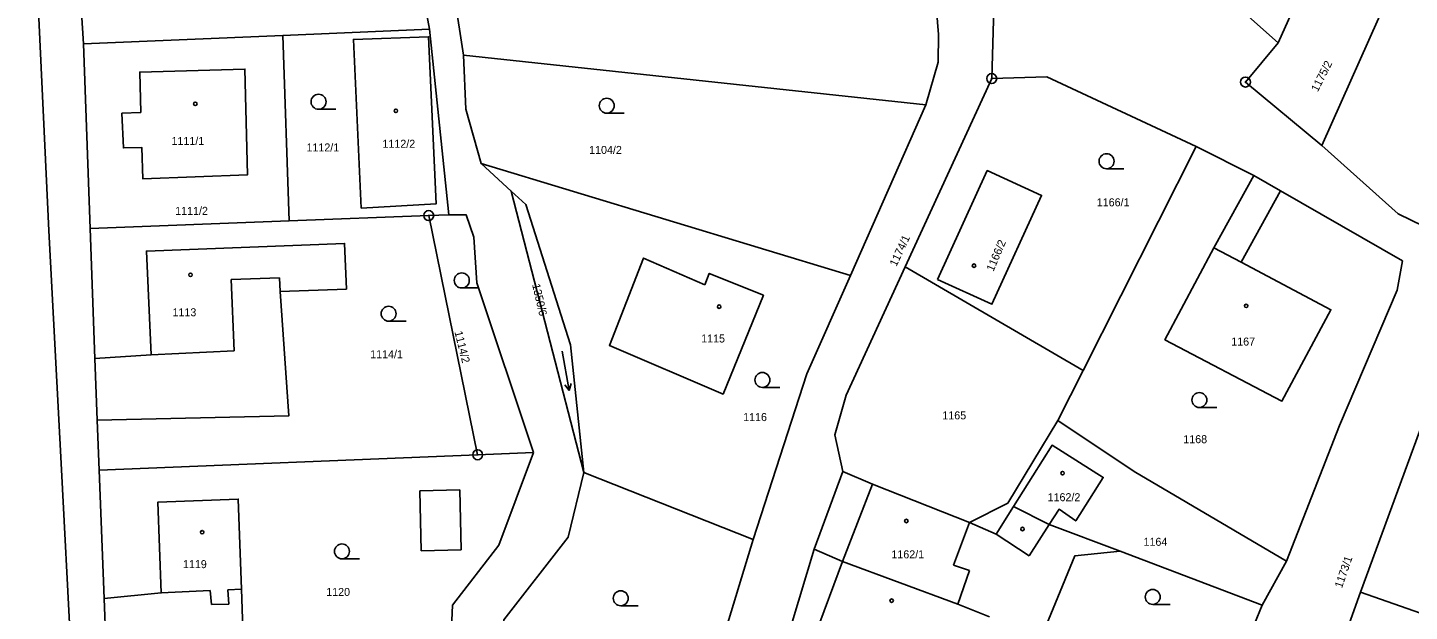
# Model space of a CAD drawing. Extents: x -587171 to -555306, y -1167727 to -1074732.
# Drawn here: x -560066 to -559927.4, y -1077139.7 to -1077081.2 of the extents above; entities that cross this region are included whole.
import ezdxf

# ---------------------------------------------------------------- set-up
doc = ezdxf.new("R2010")
doc.units = 0
for name, color, linetype in [('Hranice parcel', 7, 'Continuous'), ('Parcelní čísla', 7, 'Continuous'), ('Vnitřní kresba', 7, 'Continuous'), ('Značky bodu BP', 7, 'Continuous'), ('Značky budov', 7, 'Continuous'), ('Značky kultur', 7, 'Continuous')]:
    doc.layers.add(name, color=color, linetype=linetype)

msp = doc.modelspace()

# ---------------------------------------------------------------- linework, layer by layer
at = {"layer": 'Hranice parcel'}
for p, q in [((-560025.65, -1077081.36), (-560029.13, -1077063.25)), ((-560025.58, -1077062.46), (-560022.24, -1077083.94)), ((-560061.59, -1077064.02), (-560060.37, -1077082.81)), ((-559968.75, -1077069), (-559969.27, -1077086.3)), ((-559940.53, -1077082.73), (-559936, -1077072.54)), ((-559928.12, -1077074.97), (-559936.14, -1077093.02)), ((-560060.37, -1077082.81), (-560040.38, -1077081.98)), ((-560040.38, -1077081.98), (-560025.65, -1077081.36)), ((-560039.73, -1077100.58), (-560040.38, -1077081.98)), ((-560023.73, -1077099.96), (-560025.65, -1077081.36)), ((-560060.37, -1077082.81), (-560059.71, -1077101.35)), ((-560022.24, -1077083.94), (-559975.87, -1077088.92)), ((-559977.95, -1077105.17), (-559969.27, -1077086.3)), ((-559983.42, -1077106.05), (-559975.87, -1077088.92)), ((-559948.77, -1077093.13), (-559960.11, -1077115.58)), ((-559942.99, -1077096.02), (-559948.77, -1077093.13)), ((-560020.47, -1077094.81), (-559983.42, -1077106.05)), ((-560020.47, -1077094.81), (-560017.46, -1077097.59)), ((-559942.99, -1077096.02), (-559946.99, -1077103.27)), ((-559940.3, -1077097.56), (-559942.99, -1077096.02)), ((-560010.17, -1077125.81), (-560017.46, -1077097.59)), ((-559944.25, -1077104.72), (-559940.3, -1077097.56)), ((-559928.05, -1077104.59), (-559940.3, -1077097.56)), ((-560059.71, -1077101.35), (-560039.73, -1077100.58)), ((-560025.74, -1077100.04), (-560039.73, -1077100.58)), ((-560023.73, -1077099.96), (-560025.74, -1077100.04)), ((-560020.83, -1077124.03), (-560025.74, -1077100.04)), ((-560059.71, -1077101.35), (-560059.22, -1077114.39)), ((-559960.11, -1077115.58), (-559977.95, -1077105.17)), ((-560059.22, -1077114.39), (-560058.99, -1077120.55)), ((-559962.65, -1077120.6), (-559960.11, -1077115.58)), ((-560058.99, -1077120.55), (-560058.8, -1077125.56)), ((-560058.8, -1077125.56), (-560020.83, -1077124.03)), ((-560020.83, -1077124.03), (-560015.23, -1077123.81)), ((-560058.8, -1077125.56), (-560058.29, -1077138.46)), ((-560010.17, -1077125.81), (-559993.18, -1077132.53)), ((-559987.08, -1077133.51), (-559984.2, -1077125.72)), ((-559963.5, -1077131.03), (-559967.08, -1077129.22)), ((-559963.5, -1077131.03), (-559956.37, -1077133.7)), ((-560001.14, -1077158.62), (-559993.18, -1077132.53)), ((-559987.08, -1077133.51), (-559989.4, -1077141.14)), ((-559942.15, -1077139.11), (-559956.37, -1077133.7)), ((-559942.15, -1077139.11), (-559939.69, -1077134.69)), ((-559932.27, -1077137.8), (-559943.92, -1077169.97)), ((-559932.27, -1077137.8), (-559867.06, -1077160.72)), ((-560058.29, -1077138.46), (-560057.93, -1077147.65)), ((-559946.53, -1077149.71), (-559942.15, -1077139.11))]:
    msp.add_line(p, q, dxfattribs=at)
for points in [[(-559975.87, -1077088.92), (-559974.63, -1077084.66), (-559974.61, -1077081.87), (-559975.45, -1077071.52), (-559979.26, -1077056.83)], [(-559940.53, -1077082.73), (-559943.5, -1077080.07), (-559946.57, -1077077.52), (-559949.8, -1077075.14), (-559953.72, -1077072.62), (-559953.01, -1077070.87)], [(-560032.51, -1077099.3), (-560033.3, -1077082.38), (-560025.75, -1077082.11), (-560025, -1077098.87), (-560032.51, -1077099.3)], [(-560022.24, -1077083.94), (-560022, -1077089.38), (-560020.47, -1077094.81)], [(-559936.14, -1077093.02), (-559943.82, -1077086.65), (-559940.53, -1077082.73)], [(-560054.62, -1077089.69), (-560056.52, -1077089.78), (-560056.37, -1077093.26), (-560054.52, -1077093.2), (-560054.43, -1077096.35), (-560043.92, -1077095.97), (-560044.18, -1077085.35), (-560054.73, -1077085.65), (-560054.62, -1077089.69)], [(-559969.27, -1077086.3), (-559963.73, -1077086.13), (-559948.77, -1077093.13)], [(-559919.63, -1077104.19), (-559928.5, -1077099.87), (-559936.14, -1077093.02)], [(-559974.7, -1077106.44), (-559969.72, -1077095.53), (-559964.26, -1077098.02), (-559969.24, -1077108.93), (-559974.7, -1077106.44)], [(-560017.46, -1077097.59), (-560016, -1077098.93), (-560011.53, -1077113), (-560010.17, -1077125.81)], [(-560015.23, -1077123.81), (-560020.9, -1077106.78), (-560021.22, -1077102.2), (-560021.99, -1077099.95), (-560023.73, -1077099.96)], [(-560058.99, -1077120.55), (-560039.78, -1077120.14), (-560040.64, -1077107.67), (-560034, -1077107.41), (-560034.17, -1077102.83), (-560054.05, -1077103.61), (-560053.58, -1077114.01), (-560059.22, -1077114.39)], [(-559946.99, -1077103.27), (-559951.89, -1077112.49), (-559940.16, -1077118.64), (-559935.25, -1077109.48), (-559944.25, -1077104.72)], [(-559998.06, -1077106.98), (-560004.18, -1077104.31), (-560007.61, -1077113.07), (-559996.21, -1077117.95), (-559992.16, -1077108.04), (-559997.6, -1077105.85), (-559998.06, -1077106.98)], [(-559939.69, -1077134.69), (-559934.37, -1077121.11), (-559928.59, -1077107.52), (-559928.05, -1077104.59)], [(-559993.18, -1077132.53), (-559987.82, -1077115.9), (-559983.42, -1077106.05)], [(-559977.95, -1077105.17), (-559983.87, -1077118.06), (-559985, -1077122.04), (-559984.2, -1077125.72)], [(-559858.06, -1077126.03), (-559921.63, -1077108.87), (-559932.27, -1077137.8)], [(-559962.65, -1077120.6), (-559967.64, -1077128.87), (-559971.5, -1077130.82)], [(-559939.69, -1077134.69), (-559954.98, -1077125.71), (-559962.65, -1077120.6)], [(-560023.74, -1077148.28), (-560023.37, -1077139.12), (-560018.7, -1077133.08), (-560015.23, -1077123.81)], [(-559967.08, -1077129.22), (-559963.21, -1077123.07), (-559958.08, -1077126.3), (-559960.84, -1077130.66), (-559962.51, -1077129.49), (-559963.5, -1077131.03)], [(-560010.17, -1077125.81), (-560011.75, -1077132.31), (-560018.2, -1077140.57), (-560017.83, -1077148.74)], [(-559984.2, -1077125.72), (-559981.21, -1077126.99), (-559971.5, -1077130.82)], [(-560057.93, -1077147.65), (-560044.25, -1077145.49), (-560044.53, -1077137.5), (-560044.84, -1077128.48), (-560052.9, -1077128.77), (-560052.57, -1077137.88), (-560058.29, -1077138.46)], [(-559971.5, -1077130.82), (-559968.81, -1077131.98), (-559967.08, -1077129.22)], [(-559969.49, -1077140.3), (-559972.67, -1077139), (-559984.22, -1077134.73), (-559987.08, -1077133.51)], [(-559956.37, -1077133.7), (-559960.94, -1077134.18), (-559964.56, -1077143.04)]]:
    msp.add_lwpolyline(points, dxfattribs=at)
at = {"layer": 'Vnitřní kresba'}
for p, q in [((-560065.97, -1077055.87), (-560063.86, -1077101.54)), ((-560063.86, -1077101.54), (-560062.58, -1077125.54)), ((-559946.99, -1077103.27), (-559944.25, -1077104.72)), ((-560040.7, -1077106.27), (-560045.55, -1077106.45)), ((-560040.64, -1077107.67), (-560040.7, -1077106.27)), ((-560045.55, -1077106.45), (-560045.24, -1077113.61)), ((-560045.24, -1077113.61), (-560053.58, -1077114.01)), ((-560062.58, -1077125.54), (-560061.31, -1077149.62)), ((-559981.21, -1077126.99), (-559984.22, -1077134.73)), ((-560026.63, -1077127.64), (-560022.62, -1077127.56)), ((-560026.5, -1077133.65), (-560026.63, -1077127.64)), ((-560022.62, -1077127.56), (-560022.5, -1077133.58)), ((-559971.5, -1077130.82), (-559973.1, -1077135.1)), ((-559963.5, -1077131.03), (-559965.51, -1077134.17)), ((-559965.51, -1077134.17), (-559968.81, -1077131.98)), ((-560022.5, -1077133.58), (-560026.5, -1077133.65)), ((-559984.22, -1077134.73), (-559986.95, -1077142.03)), ((-559973.1, -1077135.1), (-559971.51, -1077135.65)), ((-559971.51, -1077135.65), (-559972.67, -1077139)), ((-560047.65, -1077137.65), (-560052.57, -1077137.88)), ((-560047.54, -1077139.05), (-560047.65, -1077137.65)), ((-560044.53, -1077137.5), (-560045.9, -1077137.56)), ((-560045.9, -1077137.56), (-560045.8, -1077139)), ((-560045.8, -1077139), (-560047.54, -1077139.05))]:
    msp.add_line(p, q, dxfattribs=at)
at = {"layer": 'Značky bodu BP'}
for centre, radius in [((-559969.27, -1077086.3), 0.5), ((-559969.27, -1077086.3), 0.0303), ((-559943.82, -1077086.65), 0.5), ((-559943.82, -1077086.65), 0.0303), ((-560025.74, -1077100.04), 0.5), ((-560025.74, -1077100.04), 0.0303), ((-560020.83, -1077124.03), 0.5), ((-560020.83, -1077124.03), 0.0303)]:
    msp.add_circle(centre, radius, dxfattribs=at)
at = {"layer": 'Značky budov'}
for centre in [(-560049.15, -1077088.84), (-560029.03, -1077089.53), (-559971.04, -1077105.07), (-560049.64, -1077105.99), (-559996.6, -1077109.18), (-559943.74, -1077109.1), (-559962.16, -1077125.87), (-559977.83, -1077130.67), (-560048.47, -1077131.8), (-559966.18, -1077131.48), (-559979.31, -1077138.66)]:
    msp.add_circle(centre, 0.175, dxfattribs=at)
at = {"layer": 'Značky kultur'}
for p, q in [((-560036.79, -1077089.38), (-560035.04, -1077089.38)), ((-560007.88, -1077089.77), (-560006.13, -1077089.77)), ((-559957.75, -1077095.34), (-559956, -1077095.34)), ((-560022.42, -1077107.3), (-560020.67, -1077107.3)), ((-560029.76, -1077110.63), (-560028.01, -1077110.63)), ((-560012.35, -1077113.63), (-560011.66, -1077117.59)), ((-560011.66, -1077117.59), (-560012.1, -1077117.01)), ((-560011.66, -1077117.59), (-560011.44, -1077116.89)), ((-559992.27, -1077117.28), (-559990.52, -1077117.28)), ((-559948.44, -1077119.29), (-559946.69, -1077119.29)), ((-560034.44, -1077134.47), (-560032.69, -1077134.47)), ((-560006.48, -1077139.17), (-560004.73, -1077139.17)), ((-559953.12, -1077139.04), (-559951.37, -1077139.04))]:
    msp.add_line(p, q, dxfattribs=at)
for centre in [(-560036.79, -1077088.63), (-560007.88, -1077089.02), (-559957.75, -1077094.59), (-560022.42, -1077106.55), (-560029.76, -1077109.88), (-559992.27, -1077116.53), (-559948.44, -1077118.54), (-560034.44, -1077133.72), (-560006.48, -1077138.42), (-559953.12, -1077138.29)]:
    msp.add_circle(centre, 0.75, dxfattribs=at)

# ---------------------------------------------------------------- texts
at = {"layer": 'Parcelní čísla'}
for s, rotation, p in [('1175/2', 63, (-559936.57, -1077087.69)), ('1174/1', 65, (-559978.83, -1077105.21)), ('1166/2', 67, (-559969.1, -1077105.71)), ('1350/6', 283, (-560015.37, -1077106.97)), ('1114/2', 284, (-560023.16, -1077111.72)), ('1173/1', 71, (-559934.14, -1077137.46))]:
    msp.add_text(s, height=0.803, rotation=rotation, dxfattribs=at).set_placement(p)
for s, p in [('1111/1', (-560051.54, -1077092.96)), ('1112/2', (-560030.38, -1077093.24)), ('1112/1', (-560038, -1077093.61)), ('1104/2', (-560009.65, -1077093.86)), ('1111/2', (-560051.17, -1077099.97)), ('1166/1', (-559958.73, -1077099.11)), ('1113', (-560051.44, -1077110.14)), ('1115', (-559998.41, -1077112.77)), ('1167', (-559945.24, -1077113.08)), ('1114/1', (-560031.61, -1077114.35)), ('1116', (-559994.2, -1077120.65)), ('1165', (-559974.22, -1077120.48)), ('1168', (-559950.05, -1077122.87)), ('1162/2', (-559963.66, -1077128.69)), ('1164', (-559954.04, -1077133.16)), ('1162/1', (-559979.33, -1077134.42)), ('1119', (-560050.39, -1077135.4)), ('1120', (-560036.02, -1077138.19))]:
    msp.add_text(s, height=0.803, dxfattribs=at).set_placement(p)

doc.saveas('drawing.dxf')
